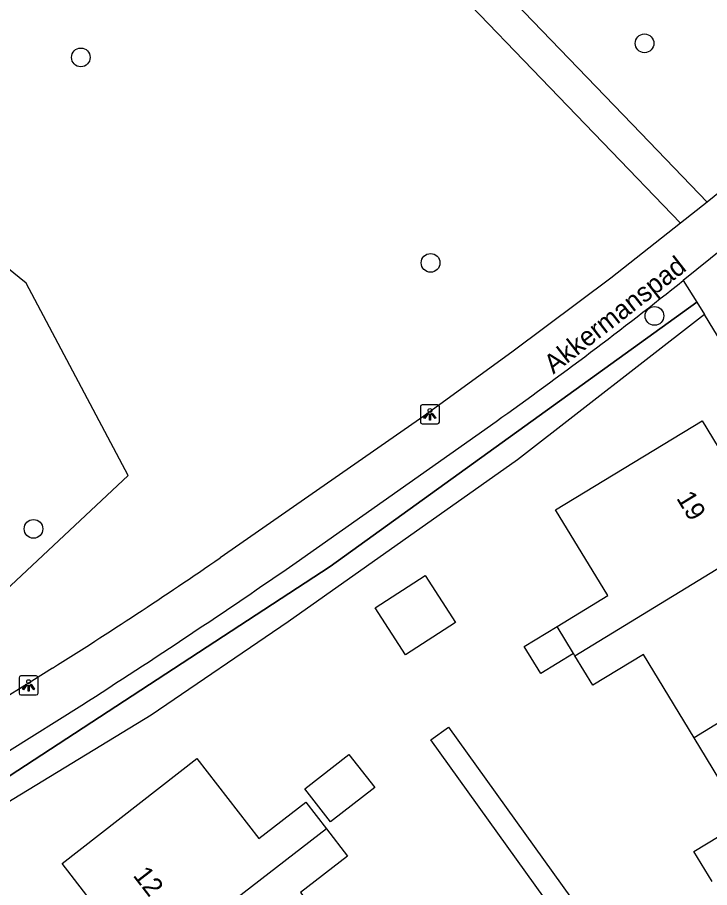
# Model space of a CAD drawing. Extents: x 162675 to 163482, y 379761 to 381227.
# Drawn here: x 163161.42 to 163197.66, y 381049.64 to 381095.17 of the extents above; entities that cross this region are included whole.
import ezdxf

# ---------------------------------------------------------------- set-up
doc = ezdxf.new("R2010")
doc.units = 0
for name, color, linetype in [('IMGEO_Boom', 7, 'Continuous'), ('IMGEO_Groenvoorziening', 7, 'Continuous'), ('IMGEO_Hek', 7, 'Continuous'), ('IMGEO_Lichtpunt', 7, 'Continuous'), ('IMGEO_Loofbos', 7, 'Continuous'), ('IMGEO_Openbare_ruimte_label', 7, 'Continuous'), ('IMGEO_Pand', 7, 'Continuous'), ('IMGEO_Pand_nummerreeks', 7, 'Continuous'), ('IMGEO_Voetpad_halfverhard', 7, 'Continuous'), ('IMGEO_Voetpad_open', 7, 'Continuous')]:
    doc.layers.add(name, color=color, linetype=linetype)

msp = doc.modelspace()

# ---------------------------------------------------------------- linework, layer by layer
at = {"layer": 'IMGEO_Boom'}
for centre in [(163194.253, 381093.814), (163164.745, 381093.079), (163183.054, 381082.329), (163194.774, 381079.552), (163162.266, 381068.411)]:
    msp.add_circle(centre, 0.489, dxfattribs=at)
at = {"layer": 'IMGEO_Groenvoorziening'}
for points in [[(163157.958, 381053.496), (163177.8, 381066.44), (163196.99, 381080.281)], [(163197.39, 381079.623), (163187.607, 381072.029), (163175.603, 381063.541), (163168.423, 381058.662), (163158.593, 381052.674)]]:
    msp.add_lwpolyline(points, dxfattribs=at)
at = {"layer": 'IMGEO_Hek'}
msp.add_lwpolyline([(163196.99, 381080.281), (163177.8, 381066.44), (163157.958, 381053.496)], dxfattribs=at)
at = {"layer": 'IMGEO_Lichtpunt'}
for p, q in [((163183.422, 381074.902), (163182.614, 381074.902)), ((163183.422, 381074.902), (163182.614, 381074.902)), ((163182.52, 381074.807), (163182.52, 381074)), ((163182.52, 381074.807), (163182.52, 381074)), ((163183.516, 381074), (163183.516, 381074.807)), ((163183.516, 381074), (163183.516, 381074.807)), ((163182.614, 381073.906), (163183.422, 381073.906)), ((163182.614, 381073.906), (163183.422, 381073.906)), ((163162.414, 381060.717), (163161.606, 381060.717)), ((163162.414, 381060.717), (163161.606, 381060.717)), ((163161.512, 381060.622), (163161.512, 381059.815)), ((163161.512, 381060.622), (163161.512, 381059.815)), ((163162.508, 381059.815), (163162.508, 381060.622)), ((163162.508, 381059.815), (163162.508, 381060.622)), ((163161.606, 381059.721), (163162.414, 381059.721)), ((163161.606, 381059.721), (163162.414, 381059.721))]:
    msp.add_line(p, q, dxfattribs=at)
for points in [[(163182.894, 381074.471), (163182.933, 381074.443), (163182.745, 381074.181), (163182.707, 381074.208), (163182.894, 381074.471)], [(163182.996, 381074.423), (163183.043, 381074.423), (163183.043, 381074.101), (163182.996, 381074.101), (163182.996, 381074.423)], [(163183.106, 381074.443), (163183.144, 381074.47), (163183.331, 381074.208), (163183.292, 381074.18), (163183.106, 381074.443)], [(163161.886, 381060.286), (163161.925, 381060.258), (163161.737, 381059.996), (163161.699, 381060.023), (163161.886, 381060.286)], [(163162.098, 381060.258), (163162.136, 381060.285), (163162.323, 381060.023), (163162.284, 381059.995), (163162.098, 381060.258)], [(163161.988, 381060.238), (163162.035, 381060.238), (163162.035, 381059.916), (163161.988, 381059.916), (163161.988, 381060.238)]]:
    msp.add_lwpolyline(points, dxfattribs=at)
for centre in [(163183.019, 381074.605), (163162.011, 381060.42)]:
    msp.add_circle(centre, 0.0994, dxfattribs=at)
for centre, start, end in [((163182.614, 381074.807), 90, 180), ((163182.614, 381074.807), 90, 180), ((163183.422, 381074.807), 0, 90), ((163183.422, 381074.807), 0, 90), ((163182.614, 381074), 180, 270), ((163182.614, 381074), 180, 270), ((163183.422, 381074), 270, 0), ((163183.422, 381074), 270, 360), ((163161.606, 381060.622), 90, 180), ((163161.606, 381060.622), 90, 180), ((163162.414, 381060.622), 0, 90), ((163162.414, 381060.622), 0, 90), ((163161.606, 381059.815), 180, 270), ((163161.606, 381059.815), 180, 270), ((163162.414, 381059.815), 270, 0), ((163162.414, 381059.815), 270, 360)]:
    msp.add_arc(centre, 0.0946, start, end, dxfattribs=at)
at = {"layer": 'IMGEO_Loofbos'}
msp.add_lwpolyline([(163152.156, 381056.698), (163158.556, 381063.09), (163167.224, 381071.204), (163161.876, 381081.272), (163151.836, 381089.391)], dxfattribs=at)
at = {"layer": 'IMGEO_Pand'}
for points in [[(163189.673, 381063.304), (163192.327, 381064.92), (163189.593, 381069.408), (163197.265, 381074.071), (163200.921, 381068.07)], [(163190.607, 381061.77), (163200.921, 381068.07)], [(163180.153, 381064.282), (163182.774, 381065.967), (163184.354, 381063.509), (163181.733, 381061.824), (163180.153, 381064.282)], [(163190.533, 381061.891), (163188.816, 381060.846), (163187.956, 381062.259), (163189.673, 381063.304)], [(163190.533, 381061.891), (163189.673, 381063.304)], [(163204.515, 381062.172), (163196.845, 381057.487)], [(163190.607, 381061.77), (163190.533, 381061.891)], [(163196.845, 381057.487), (163194.191, 381061.844), (163191.544, 381060.232), (163190.607, 381061.77)], [(163197.786, 381049.969), (163196.839, 381051.524), (163199.492, 381053.14), (163196.845, 381057.487)], [(163168.065, 381045.341), (163163.768, 381050.906), (163170.824, 381056.405), (163174.064, 381052.219), (163176.518, 381054.118), (163177.61, 381052.709)], [(163178.782, 381056.608), (163180.127, 381054.872), (163177.814, 381053.08), (163176.469, 381054.815), (163178.782, 381056.608)], [(163177.61, 381052.709), (163168.065, 381045.341)], [(163177.61, 381052.709), (163178.706, 381051.294), (163176.245, 381049.39), (163179.376, 381045.345)]]:
    msp.add_lwpolyline(points, dxfattribs=at)
at = {"layer": 'IMGEO_Voetpad_halfverhard'}
for points in [[(163197.533, 381085.509), (163194.064, 381089.109), (163181.838, 381101.796)], [(163181.471, 381099.638), (163192.068, 381088.633), (163196.141, 381084.403)]]:
    msp.add_lwpolyline(points, dxfattribs=at)
at = {"layer": 'IMGEO_Voetpad_open'}
for points in [[(163212.113, 381097.704), (163206.811, 381093.132), (163201.94, 381089.082), (163197.533, 381085.509)], [(163197.533, 381085.509), (163196.141, 381084.403)], [(163200.571, 381084.851), (163196.28, 381081.408)], [(163196.141, 381084.403), (163192.481, 381081.536), (163187.377, 381077.705), (163182.692, 381074.309), (163172.038, 381066.893)], [(163196.28, 381081.408), (163196.99, 381080.281)], [(163196.99, 381080.281), (163197.39, 381079.623)], [(163210.472, 381058.155), (163197.39, 381079.623)], [(163176.013, 381066.649), (163186.479, 381074.025)], [(163163.253, 381061.119), (163162.172, 381060.44), (163153.181, 381054.858)], [(163157.199, 381054.441), (163164.797, 381059.191)], [(163197.985, 381036.604), (163183.06, 381057.381), (163183.983, 381058.045), (163198.909, 381037.268)]]:
    msp.add_lwpolyline(points, dxfattribs=at)
for centre, radius, start, end in [((163053.472, 381260.789), 229.285, 305.45704, 308.5237), ((163024.424, 381281.914), 260.814, 302.1604, 304.46997), ((162960.822, 381378.11), 378.57, 302.60232, 304.64096)]:
    msp.add_arc(centre, radius, start, end, dxfattribs=at)

# ---------------------------------------------------------------- texts
at = {"layer": 'IMGEO_Openbare_ruimte_label'}
msp.add_text('Akkermanspad', height=1, rotation=37.9705, dxfattribs=at).set_placement((163189.482, 381076.483))
at = {"layer": 'IMGEO_Pand_nummerreeks'}
for s, rotation, p in [('19', 301.3578, (163195.894, 381070.018)), ('12', 307.6711, (163167.441, 381050.272))]:
    msp.add_text(s, height=1, rotation=rotation, dxfattribs=at).set_placement(p)

doc.saveas('drawing.dxf')
